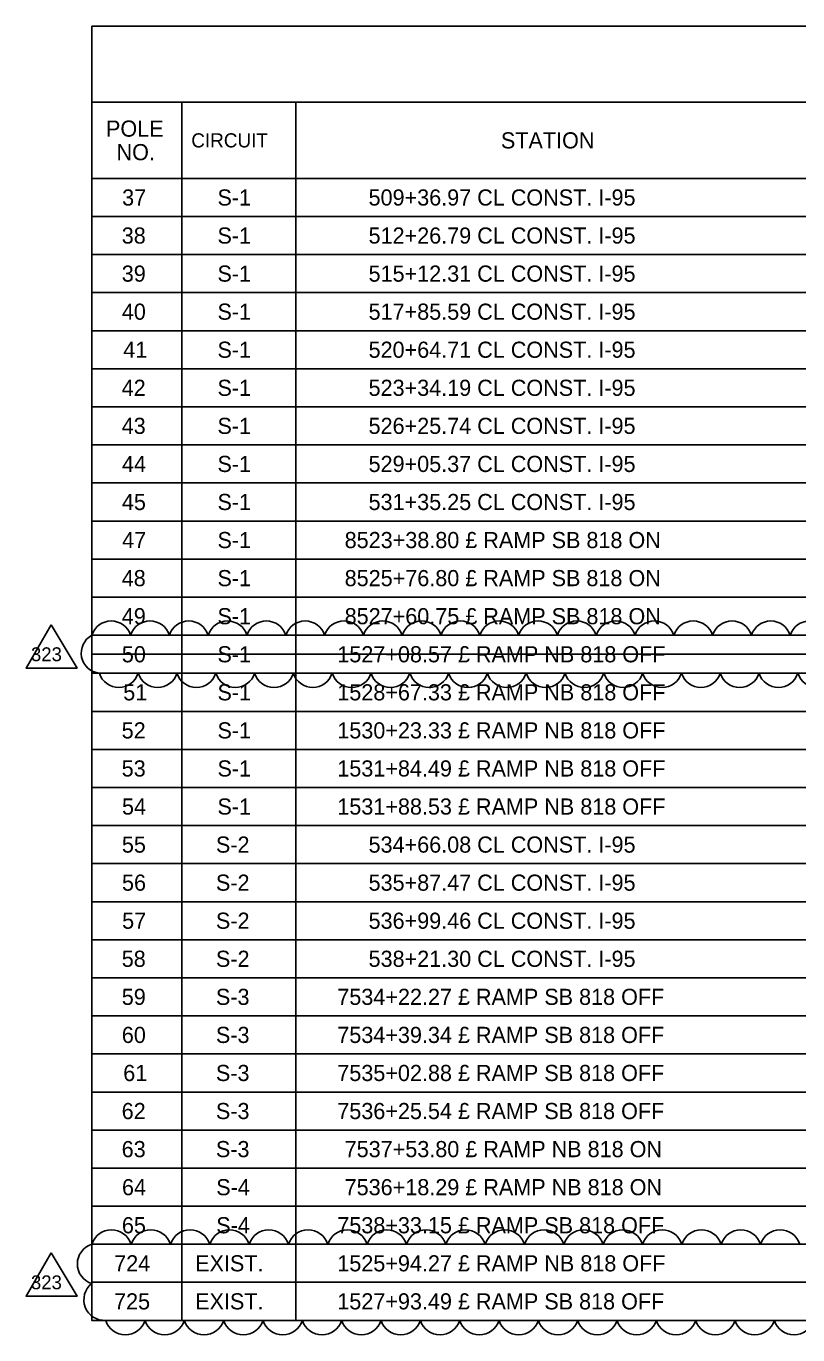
# Model space of a CAD drawing. Extents: x -816.7 to -800.7, y -2197.9 to -2187.9.
# Drawn here: x -808.45 to -805.1, y -2193.53 to -2187.86 of the extents above; entities that cross this region are included whole.
import ezdxf

# ---------------------------------------------------------------- set-up
doc = ezdxf.new("R2010")
doc.units = 0
for name, color, linetype in [('Cloud_dp', 7, 'Continuous'), ('NonPlottingEle_dp', 7, 'Continuous'), ('SumBoxBorder_dp', 7, 'Continuous'), ('SumBoxLines_dp', 7, 'Continuous'), ('SumBoxLinesMin_dp', 7, 'Continuous'), ('TextLabel', 7, 'Continuous')]:
    doc.layers.add(name, color=color, linetype=linetype)

msp = doc.modelspace()

# ---------------------------------------------------------------- linework, layer by layer
at = {"layer": 'Cloud_dp'}
msp.add_line((-808.1636, -2190.5787), (-800.7686, -2190.5787), dxfattribs=at)
for points in [[(-808.3404, -2190.4508), (-808.4481, -2190.6388), (-808.2275, -2190.6388)], [(-808.3404, -2193.1733), (-808.4481, -2193.3613), (-808.2275, -2193.3613)]]:
    msp.add_lwpolyline(points, close=True, dxfattribs=at)
for centre, radius, start, end in [((-808.0794, -2190.5227), 0.0882, 17.5, 162.5), ((-807.9112, -2190.5227), 0.0882, 17.5, 162.5), ((-807.7429, -2190.5227), 0.0882, 17.5, 162.5), ((-807.5746, -2190.5227), 0.0882, 17.5, 162.5), ((-807.4064, -2190.5227), 0.0882, 17.5, 162.5), ((-807.2381, -2190.5227), 0.0882, 17.5, 162.5), ((-807.0698, -2190.5227), 0.0882, 17.5, 162.5), ((-806.9016, -2190.5227), 0.0882, 17.5, 162.5), ((-806.7333, -2190.5227), 0.0882, 17.5, 162.5), ((-806.565, -2190.5227), 0.0882, 17.5, 162.5), ((-806.3968, -2190.5227), 0.0882, 17.5, 162.5), ((-806.2285, -2190.5227), 0.0882, 17.5, 162.5), ((-806.0602, -2190.5227), 0.0882, 17.5, 162.5), ((-805.8919, -2190.5227), 0.0882, 17.5, 162.5), ((-805.7237, -2190.5227), 0.0882, 17.5, 162.5), ((-805.5554, -2190.5227), 0.0882, 17.5, 162.5), ((-805.3871, -2190.5227), 0.0882, 17.5, 162.5), ((-805.2189, -2190.5227), 0.0882, 17.5, 162.5), ((-805.0506, -2190.5227), 0.0882, 17.5, 162.5), ((-808.1211, -2190.5735), 0.0882, 118.7989, 263.7989), ((-808.0465, -2190.6347), 0.0882, 197.5, 342.5), ((-807.8782, -2190.6347), 0.0882, 197.5, 342.5), ((-807.7099, -2190.6347), 0.0882, 197.5, 342.5), ((-807.5417, -2190.6347), 0.0882, 197.5, 342.5), ((-807.3734, -2190.6347), 0.0882, 197.5, 342.5), ((-807.2051, -2190.6347), 0.0882, 197.5, 342.5), ((-807.0369, -2190.6347), 0.0882, 197.5, 342.5), ((-806.8686, -2190.6347), 0.0882, 197.5, 342.5), ((-806.7003, -2190.6347), 0.0882, 197.5, 342.5), ((-806.5321, -2190.6347), 0.0882, 197.5, 342.5), ((-806.3638, -2190.6347), 0.0882, 197.5, 342.5), ((-806.1955, -2190.6347), 0.0882, 197.5, 342.5), ((-806.0272, -2190.6347), 0.0882, 197.5, 342.5), ((-805.859, -2190.6347), 0.0882, 197.5, 342.5), ((-805.6907, -2190.6347), 0.0882, 197.5, 342.5), ((-805.5224, -2190.6347), 0.0882, 197.5, 342.5), ((-805.3542, -2190.6347), 0.0882, 197.5, 342.5), ((-805.1859, -2190.6347), 0.0882, 197.5, 342.5), ((-805.0176, -2190.6347), 0.0882, 197.5, 342.5), ((-808.0783, -2193.1631), 0.0894, 17.5, 162.5), ((-807.9077, -2193.1631), 0.0894, 17.5, 162.5), ((-807.7371, -2193.1631), 0.0894, 17.5, 162.5), ((-807.5666, -2193.1631), 0.0894, 17.5, 162.5), ((-807.396, -2193.1631), 0.0894, 17.5, 162.5), ((-807.2254, -2193.1631), 0.0894, 17.5, 162.5), ((-807.0548, -2193.1631), 0.0894, 17.5, 162.5), ((-806.8843, -2193.1631), 0.0894, 17.5, 162.5), ((-806.7137, -2193.1631), 0.0894, 17.5, 162.5), ((-806.5431, -2193.1631), 0.0894, 17.5, 162.5), ((-806.3725, -2193.1631), 0.0894, 17.5, 162.5), ((-806.202, -2193.1631), 0.0894, 17.5, 162.5), ((-806.0314, -2193.1631), 0.0894, 17.5, 162.5), ((-805.8608, -2193.1631), 0.0894, 17.5, 162.5), ((-805.6902, -2193.1631), 0.0894, 17.5, 162.5), ((-805.5197, -2193.1631), 0.0894, 17.5, 162.5), ((-805.3491, -2193.1631), 0.0894, 17.5, 162.5), ((-805.1785, -2193.1631), 0.0894, 17.5, 162.5), ((-808.1367, -2193.2215), 0.0894, 107.5, 252.5), ((-808.1083, -2193.377), 0.0894, 128.2038, 273.2038), ((-808.018, -2193.4393), 0.0894, 197.5, 342.5), ((-807.8475, -2193.4393), 0.0894, 197.5, 342.5), ((-807.6769, -2193.4393), 0.0894, 197.5, 342.5), ((-807.5063, -2193.4393), 0.0894, 197.5, 342.5), ((-807.3357, -2193.4393), 0.0894, 197.5, 342.5), ((-807.1652, -2193.4393), 0.0894, 197.5, 342.5), ((-806.9946, -2193.4393), 0.0894, 197.5, 342.5), ((-806.824, -2193.4393), 0.0894, 197.5, 342.5), ((-806.6534, -2193.4393), 0.0894, 197.5, 342.5), ((-806.4829, -2193.4393), 0.0894, 197.5, 342.5), ((-806.3123, -2193.4393), 0.0894, 197.5, 342.5), ((-806.1417, -2193.4393), 0.0894, 197.5, 342.5), ((-805.9711, -2193.4393), 0.0894, 197.5, 342.5), ((-805.8006, -2193.4393), 0.0894, 197.5, 342.5), ((-805.63, -2193.4393), 0.0894, 197.5, 342.5), ((-805.4594, -2193.4393), 0.0894, 197.5, 342.5), ((-805.2888, -2193.4393), 0.0894, 197.5, 342.5), ((-805.1183, -2193.4393), 0.0894, 197.5, 342.5)]:
    msp.add_arc(centre, radius, start, end, dxfattribs=at)
at = {"layer": 'NonPlottingEle_dp'}
for points in [[(-808.1636, -2190.4962), (-800.7686, -2190.4962), (-800.7686, -2190.6612), (-808.1636, -2190.6612)], [(-808.1636, -2193.1362), (-800.7686, -2193.1362), (-800.7686, -2193.4662), (-808.1636, -2193.4662)]]:
    msp.add_lwpolyline(points, close=True, dxfattribs=at)
at = {"layer": 'SumBoxBorder_dp'}
for p, q in [((-808.1636, -2187.8562), (-800.7686, -2187.8562)), ((-808.1636, -2187.8562), (-808.1636, -2193.4662)), ((-808.1636, -2188.1862), (-800.7686, -2188.1862)), ((-808.1636, -2188.1862), (-800.7686, -2188.1862)), ((-808.1636, -2193.4662), (-800.7686, -2193.4662)), ((-808.1636, -2193.4662), (-800.7686, -2193.4662))]:
    msp.add_line(p, q, dxfattribs=at)
at = {"layer": 'SumBoxLines_dp'}
for p, q in [((-807.7736, -2188.1862), (-807.7736, -2193.4662)), ((-807.7736, -2188.1862), (-807.7736, -2193.4662)), ((-807.2786, -2188.1862), (-807.2786, -2191.9812)), ((-807.2786, -2188.1862), (-807.2786, -2193.4662)), ((-808.1636, -2188.5162), (-800.7686, -2188.5162)), ((-807.2786, -2192.1462), (-807.2786, -2192.3112)), ((-807.2786, -2192.4762), (-807.2786, -2192.6412)), ((-807.2786, -2192.8062), (-807.2786, -2193.4662))]:
    msp.add_line(p, q, dxfattribs=at)
at = {"layer": 'SumBoxLinesMin_dp'}
for p, q in [((-808.1636, -2188.5162), (-800.7686, -2188.5162)), ((-808.1636, -2188.6812), (-800.7686, -2188.6812)), ((-808.1636, -2188.6812), (-800.7686, -2188.6812)), ((-808.1636, -2188.8462), (-800.7686, -2188.8462)), ((-808.1636, -2188.8462), (-800.7686, -2188.8462)), ((-808.1636, -2189.0112), (-800.7686, -2189.0112)), ((-808.1636, -2189.0112), (-800.7686, -2189.0112)), ((-808.1636, -2189.1762), (-800.7686, -2189.1762)), ((-808.1636, -2189.1762), (-800.7686, -2189.1762)), ((-808.1636, -2189.3412), (-800.7686, -2189.3412)), ((-808.1636, -2189.3412), (-800.7686, -2189.3412)), ((-808.1636, -2189.5062), (-800.7686, -2189.5062)), ((-808.1636, -2189.5062), (-800.7686, -2189.5062)), ((-808.1636, -2189.6712), (-800.7686, -2189.6712)), ((-808.1636, -2189.6712), (-800.7686, -2189.6712)), ((-808.1636, -2189.8362), (-800.7686, -2189.8362)), ((-808.1636, -2189.8362), (-800.7686, -2189.8362)), ((-808.1636, -2190.0012), (-800.7686, -2190.0012)), ((-808.1636, -2190.0012), (-800.7686, -2190.0012)), ((-808.1636, -2190.1662), (-800.7686, -2190.1662)), ((-808.1636, -2190.1662), (-800.7686, -2190.1662)), ((-808.1636, -2190.3312), (-800.7686, -2190.3312)), ((-808.1636, -2190.3312), (-800.7686, -2190.3312)), ((-808.1636, -2190.4962), (-800.7686, -2190.4962)), ((-808.1636, -2190.4962), (-800.7686, -2190.4962)), ((-808.1636, -2190.6612), (-800.7686, -2190.6612)), ((-808.1636, -2190.6612), (-800.7686, -2190.6612)), ((-808.1636, -2190.8262), (-800.7686, -2190.8262)), ((-808.1636, -2190.8262), (-800.7686, -2190.8262)), ((-808.1636, -2190.9912), (-800.7686, -2190.9912)), ((-808.1636, -2190.9912), (-800.7686, -2190.9912)), ((-808.1636, -2191.1562), (-800.7686, -2191.1562)), ((-808.1636, -2191.1562), (-800.7686, -2191.1562)), ((-808.1636, -2191.3212), (-800.7686, -2191.3212)), ((-808.1636, -2191.3212), (-800.7686, -2191.3212)), ((-808.1636, -2191.4862), (-800.7686, -2191.4862)), ((-808.1636, -2191.4862), (-800.7686, -2191.4862)), ((-808.1636, -2191.6512), (-807.2786, -2191.6512)), ((-808.1636, -2191.6512), (-800.7686, -2191.6512)), ((-808.1636, -2191.8162), (-800.7686, -2191.8162)), ((-808.1636, -2191.8162), (-800.7686, -2191.8162)), ((-808.1636, -2191.9812), (-800.7686, -2191.9812)), ((-808.1636, -2191.9812), (-800.7686, -2191.9812)), ((-808.1636, -2192.1462), (-807.7736, -2192.1462)), ((-808.1636, -2192.1462), (-800.7686, -2192.1462)), ((-807.2786, -2192.1462), (-804.0161, -2192.1462)), ((-808.1636, -2192.3112), (-800.7686, -2192.3112)), ((-808.1636, -2192.3112), (-800.7686, -2192.3112)), ((-808.1636, -2192.4762), (-807.7736, -2192.4762)), ((-808.1636, -2192.4762), (-800.7686, -2192.4762)), ((-808.1636, -2192.6412), (-800.7686, -2192.6412)), ((-808.1636, -2192.6412), (-800.7686, -2192.6412)), ((-808.1636, -2192.8062), (-807.7736, -2192.8062)), ((-808.1636, -2192.8062), (-800.7686, -2192.8062)), ((-808.1636, -2192.9712), (-800.7686, -2192.9712)), ((-808.1636, -2192.9712), (-800.7686, -2192.9712)), ((-808.1636, -2193.1362), (-800.7686, -2193.1362)), ((-808.1636, -2193.1362), (-800.7686, -2193.1362)), ((-808.1636, -2193.3012), (-800.7686, -2193.3012)), ((-808.1636, -2193.3012), (-800.7686, -2193.3012))]:
    msp.add_line(p, q, dxfattribs=at)

# ---------------------------------------------------------------- texts
at = {"layer": 'Cloud_dp'}
for p in [(-808.4272, -2190.6087), (-808.4272, -2193.3312)]:
    msp.add_text('323', height=0.05998, rotation=0, dxfattribs=at).set_placement(p)
at = {"layer": 'TextLabel'}
for s, height, p in [('POLE', 0.07, (-808.1019, -2188.3352)), ('CIRCUIT', 0.06125, (-807.732, -2188.3818)), ('STATION', 0.07, (-806.3894, -2188.3862)), ('NO.', 0.07, (-808.0562, -2188.4372)), ('37', 0.07, (-808.0319, -2188.6337)), ('S-1', 0.07, (-807.6185, -2188.6337)), ('509+36.97 CL CONST. I-95', 0.07, (-806.9633, -2188.6337)), ('38', 0.07, (-808.0336, -2188.7987)), ('S-1', 0.07, (-807.6185, -2188.7987)), ('512+26.79 CL CONST. I-95', 0.07, (-806.9633, -2188.7987)), ('39', 0.07, (-808.0335, -2188.9637)), ('S-1', 0.07, (-807.6185, -2188.9637)), ('515+12.31 CL CONST. I-95', 0.07, (-806.9633, -2188.9637)), ('40', 0.07, (-808.0333, -2189.1287)), ('S-1', 0.07, (-807.6185, -2189.1287)), ('517+85.59 CL CONST. I-95', 0.07, (-806.9633, -2189.1287)), ('41', 0.07, (-808.0271, -2189.2937)), ('S-1', 0.07, (-807.6185, -2189.2937)), ('520+64.71 CL CONST. I-95', 0.07, (-806.9633, -2189.2937)), ('42', 0.07, (-808.0339, -2189.4587)), ('S-1', 0.07, (-807.6185, -2189.4587)), ('523+34.19 CL CONST. I-95', 0.07, (-806.9633, -2189.4587)), ('43', 0.07, (-808.0339, -2189.6237)), ('S-1', 0.07, (-807.6185, -2189.6237)), ('526+25.74 CL CONST. I-95', 0.07, (-806.9633, -2189.6237)), ('44', 0.07, (-808.0325, -2189.7887)), ('S-1', 0.07, (-807.6185, -2189.7887)), ('529+05.37 CL CONST. I-95', 0.07, (-806.9633, -2189.7887)), ('45', 0.07, (-808.033, -2189.9537)), ('S-1', 0.07, (-807.6185, -2189.9537)), ('531+35.25 CL CONST. I-95', 0.07, (-806.9633, -2189.9537)), ('47', 0.07, (-808.0319, -2190.1187)), ('S-1', 0.07, (-807.6185, -2190.1187)), ('8523+38.80 £ RAMP SB 818 ON', 0.07, (-807.067, -2190.1187)), ('48', 0.07, (-808.0336, -2190.2837)), ('S-1', 0.07, (-807.6185, -2190.2837)), ('8525+76.80 £ RAMP SB 818 ON', 0.07, (-807.067, -2190.2837)), ('49', 0.07, (-808.0335, -2190.4487)), ('S-1', 0.07, (-807.6185, -2190.4487)), ('8527+60.75 £ RAMP SB 818 ON', 0.07, (-807.067, -2190.4487)), ('50', 0.07, (-808.0333, -2190.6137)), ('S-1', 0.07, (-807.6185, -2190.6137)), ('1527+08.57 £ RAMP NB 818 OFF', 0.07, (-807.0989, -2190.6137)), ('51', 0.07, (-808.0271, -2190.7787)), ('S-1', 0.07, (-807.6185, -2190.7787)), ('1528+67.33 £ RAMP NB 818 OFF', 0.07, (-807.0989, -2190.7787)), ('52', 0.07, (-808.0339, -2190.9437)), ('S-1', 0.07, (-807.6185, -2190.9437)), ('1530+23.33 £ RAMP NB 818 OFF', 0.07, (-807.0989, -2190.9437)), ('53', 0.07, (-808.0339, -2191.1087)), ('S-1', 0.07, (-807.6185, -2191.1087)), ('1531+84.49 £ RAMP NB 818 OFF', 0.07, (-807.0989, -2191.1087)), ('54', 0.07, (-808.0325, -2191.2737)), ('S-1', 0.07, (-807.6185, -2191.2737)), ('1531+88.53 £ RAMP NB 818 OFF', 0.07, (-807.0989, -2191.2737)), ('55', 0.07, (-808.033, -2191.4387)), ('S-2', 0.07, (-807.6252, -2191.4387)), ('534+66.08 CL CONST. I-95', 0.07, (-806.9633, -2191.4387)), ('56', 0.07, (-808.0325, -2191.6037)), ('S-2', 0.07, (-807.6252, -2191.6037)), ('535+87.47 CL CONST. I-95', 0.07, (-806.9633, -2191.6037)), ('57', 0.07, (-808.0319, -2191.7687)), ('S-2', 0.07, (-807.6252, -2191.7687)), ('536+99.46 CL CONST. I-95', 0.07, (-806.9633, -2191.7687)), ('58', 0.07, (-808.0336, -2191.9337)), ('S-2', 0.07, (-807.6252, -2191.9337)), ('538+21.30 CL CONST. I-95', 0.07, (-806.9633, -2191.9337)), ('59', 0.07, (-808.0335, -2192.0987)), ('S-3', 0.07, (-807.6253, -2192.0987)), ('7534+22.27 £ RAMP SB 818 OFF', 0.07, (-807.0989, -2192.0987)), ('60', 0.07, (-808.0333, -2192.2637)), ('S-3', 0.07, (-807.6253, -2192.2637)), ('7534+39.34 £ RAMP SB 818 OFF', 0.07, (-807.0989, -2192.2637)), ('61', 0.07, (-808.0271, -2192.4287)), ('S-3', 0.07, (-807.6253, -2192.4287)), ('7535+02.88 £ RAMP SB 818 OFF', 0.07, (-807.0989, -2192.4287)), ('62', 0.07, (-808.0339, -2192.5937)), ('S-3', 0.07, (-807.6253, -2192.5937)), ('7536+25.54 £ RAMP SB 818 OFF', 0.07, (-807.0989, -2192.5937)), ('63', 0.07, (-808.0339, -2192.7587)), ('S-3', 0.07, (-807.6253, -2192.7587)), ('7537+53.80 £ RAMP NB 818 ON', 0.07, (-807.067, -2192.7587)), ('64', 0.07, (-808.0325, -2192.9237)), ('S-4', 0.07, (-807.6239, -2192.9237)), ('7536+18.29 £ RAMP NB 818 ON', 0.07, (-807.067, -2192.9237)), ('65', 0.07, (-808.033, -2193.0887)), ('S-4', 0.07, (-807.6239, -2193.0887)), ('7538+33.15 £ RAMP SB 818 OFF', 0.07, (-807.0989, -2193.0887)), ('724', 0.07, (-808.0664, -2193.2537)), ('EXIST.', 0.07, (-807.7154, -2193.2537)), ('1525+94.27 £ RAMP NB 818 OFF', 0.07, (-807.0989, -2193.2537)), ('725', 0.07, (-808.0669, -2193.4187)), ('EXIST.', 0.07, (-807.7154, -2193.4187)), ('1527+93.49 £ RAMP SB 818 OFF', 0.07, (-807.0989, -2193.4187))]:
    msp.add_text(s, height=height, dxfattribs=at).set_placement(p)

doc.saveas('drawing.dxf')
